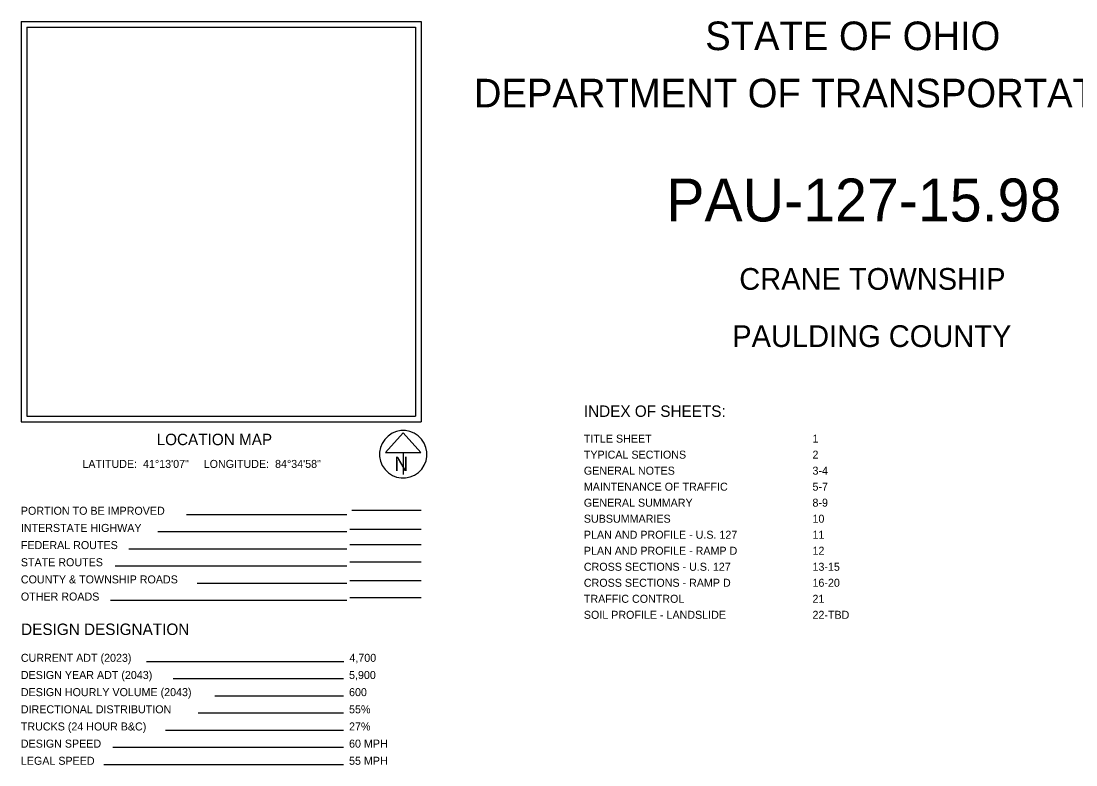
# Model space of a CAD drawing. Extents: x 0 to 64.8, y -5 to 22.
# Drawn here: x 34.99 to 53.44, y 8 to 21.01 of the extents above; entities that cross this region are included whole.
import ezdxf

# ---------------------------------------------------------------- set-up
doc = ezdxf.new("R2010")
doc.units = 0
doc.layers.add('SH_Data', color=7, linetype='Continuous')
doc.layers.add('SH_Text', color=7, linetype='Continuous')

msp = doc.modelspace()

# ---------------------------------------------------------------- linework, layer by layer
at = {"layer": 'SH_Data'}
for p, q in [((34.989, 21), (41.989, 21)), ((34.989, 21), (34.989, 14)), ((35.089, 20.9), (35.089, 14.1)), ((35.089, 20.9), (41.889, 20.9)), ((41.889, 20.9), (41.889, 14.1)), ((41.989, 21), (41.989, 14)), ((35.089, 14.1), (41.889, 14.1)), ((34.989, 14), (41.989, 14)), ((41.674, 13.809), (41.366, 13.468)), ((41.981, 13.468), (41.674, 13.809)), ((41.366, 13.468), (41.981, 13.468)), ((41.674, 13.468), (41.674, 13.081)), ((41.674, 13.435), (41.674, 13.435)), ((41.674, 13.435), (41.674, 13.435)), ((40.689, 12.377), (37.883, 12.377)), ((40.772, 12.455), (41.989, 12.455)), ((40.689, 12.077), (37.379, 12.077)), ((41.989, 12.121), (40.739, 12.121)), ((41.989, 11.849), (40.739, 11.849)), ((40.689, 11.777), (36.875, 11.777)), ((40.689, 11.477), (36.634, 11.477)), ((41.989, 11.549), (40.739, 11.549)), ((40.689, 11.177), (38.068, 11.177)), ((41.989, 11.222), (40.739, 11.222)), ((41.989, 10.922), (40.739, 10.922)), ((40.689, 10.877), (36.555, 10.877)), ((40.632, 9.806), (37.183, 9.806)), ((40.626, 9.506), (37.649, 9.506)), ((40.626, 9.206), (38.375, 9.206)), ((40.626, 8.906), (38.088, 8.906)), ((40.626, 8.606), (37.515, 8.606)), ((40.626, 8.306), (36.593, 8.306)), ((40.626, 8.006), (36.438, 8.006))]:
    msp.add_line(p, q, dxfattribs=at)
msp.add_arc((41.674, 13.435), 0.415, 129.7798, 129.7633, dxfattribs=at)

# ---------------------------------------------------------------- texts
for s, height, p in [('N', 0.25, (41.519, 13.144)), ('DESIGN DESIGNATION', 0.2, (34.989, 10.275))]:
    msp.add_text(s, height=height, dxfattribs=at).set_placement(p)
at = {"layer": 'SH_Text'}
for s, height, p in [('STATE OF OHIO', 0.5, (46.957, 20.5)), ('DEPARTMENT OF TRANSPORTATION', 0.5, (42.909, 19.5)), ('PAU-127-15.98', 0.75, (46.275, 17.505)), ('CRANE TOWNSHIP', 0.38, (47.553, 16.31)), ('PAULDING COUNTY', 0.38, (47.43, 15.31)), ('INDEX OF SHEETS:', 0.2, (44.834, 14.088)), ('LOCATION MAP', 0.2, (37.359, 13.594)), ('TITLE SHEET', 0.14, (44.834, 13.638)), ('1', 0.14, (48.834, 13.638)), ('TYPICAL SECTIONS', 0.14, (44.834, 13.358)), ('2', 0.14, (48.834, 13.358)), ('LATITUDE:  41°13\'07"     LONGITUDE:  84°34\'58"', 0.14, (36.06, 13.196)), ('GENERAL NOTES', 0.14, (44.834, 13.078)), ('3-4', 0.14, (48.834, 13.078)), ('MAINTENANCE OF TRAFFIC', 0.14, (44.834, 12.798)), ('5-7', 0.14, (48.834, 12.798)), ('GENERAL SUMMARY', 0.14, (44.834, 12.518)), ('8-9', 0.14, (48.834, 12.518)), ('PORTION TO BE IMPROVED', 0.14, (34.984, 12.377)), ('SUBSUMMARIES', 0.14, (44.834, 12.238)), ('10', 0.14, (48.834, 12.238)), ('INTERSTATE HIGHWAY', 0.14, (34.984, 12.077)), ('PLAN AND PROFILE - U.S. 127', 0.14, (44.834, 11.958)), ('11', 0.14, (48.834, 11.958)), ('FEDERAL ROUTES', 0.14, (34.984, 11.777)), ('PLAN AND PROFILE - RAMP D', 0.14, (44.834, 11.678)), ('12', 0.14, (48.834, 11.678)), ('STATE ROUTES', 0.14, (34.984, 11.477)), ('CROSS SECTIONS - U.S. 127', 0.14, (44.834, 11.398)), ('13-15', 0.14, (48.834, 11.398)), ('COUNTY & TOWNSHIP ROADS', 0.14, (34.984, 11.177)), ('CROSS SECTIONS - RAMP D', 0.14, (44.834, 11.118)), ('16-20', 0.14, (48.834, 11.118)), ('OTHER ROADS', 0.14, (34.984, 10.877)), ('TRAFFIC CONTROL', 0.14, (44.834, 10.838)), ('21', 0.14, (48.834, 10.838)), ('SOIL PROFILE - LANDSLIDE', 0.14, (44.834, 10.558)), ('22-TBD', 0.14, (48.834, 10.558)), ('CURRENT ADT (2023)', 0.14, (34.984, 9.806)), ('4,700', 0.14, (40.732, 9.806)), ('DESIGN YEAR ADT (2043)', 0.14, (34.984, 9.506)), ('5,900', 0.14, (40.726, 9.506)), ('DESIGN HOURLY VOLUME (2043)', 0.14, (34.984, 9.206)), ('600', 0.14, (40.726, 9.206)), ('DIRECTIONAL DISTRIBUTION', 0.14, (34.984, 8.906)), ('55%', 0.14, (40.726, 8.906)), ('TRUCKS (24 HOUR B&C)', 0.14, (34.984, 8.606)), ('27%', 0.14, (40.726, 8.606)), ('DESIGN SPEED', 0.14, (34.984, 8.306)), ('60 MPH', 0.14, (40.726, 8.306)), ('LEGAL SPEED', 0.14, (34.984, 8.006)), ('55 MPH', 0.14, (40.726, 8.006))]:
    msp.add_text(s, height=height, dxfattribs=at).set_placement(p)

doc.saveas('drawing.dxf')
